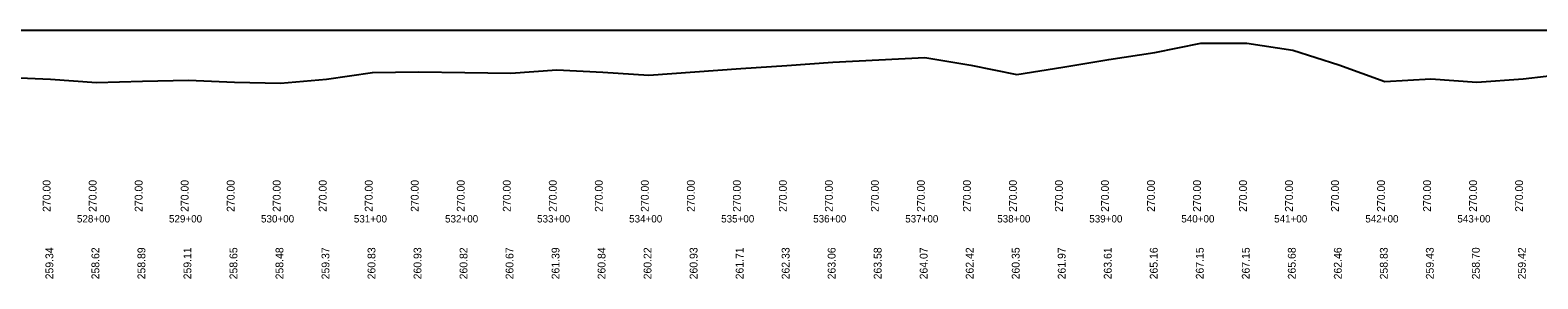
# Model space of a CAD drawing. Extents: x 1354 to 11940, y 17935 to 18885.
# Drawn here: x 6668 to 8306, y 17938 to 18209 of the extents above; entities that cross this region are included whole.
import ezdxf

# ---------------------------------------------------------------- set-up
doc = ezdxf.new("R2010")
doc.units = 0
for name, color, linetype in [('Level 40', 7, 'Continuous'), ('Level 42', 7, 'Continuous'), ('Level 43', 7, 'Continuous'), ('Level 45', 7, 'Continuous')]:
    doc.layers.add(name, color=color, linetype=linetype)

msp = doc.modelspace()

# ---------------------------------------------------------------- linework, layer by layer
at = {"layer": 'Level 40'}
msp.add_lwpolyline([(6639.7, 18157.3), (6689.7, 18155.2), (6739.7, 18151.6), (6789.7, 18153), (6839.7, 18154), (6889.7, 18151.8), (6939.7, 18150.9), (6989.7, 18155.3), (7039.7, 18162.6), (7089.7, 18163.2), (7139.7, 18162.6), (7189.7, 18161.8), (7239.7, 18165.4), (7289.7, 18162.7), (7339.7, 18159.6), (7389.7, 18163.1), (7439.7, 18167), (7489.7, 18170.2), (7539.7, 18173.8), (7589.7, 18176.4), (7639.7, 18178.8), (7689.7, 18170.6), (7739.7, 18160.2), (7789.7, 18168.3), (7839.7, 18176.5), (7889.7, 18184.3), (7939.7, 18194.3), (7989.7, 18194.3), (8039.7, 18186.9), (8089.7, 18170.8), (8139.7, 18152.7), (8189.7, 18155.6), (8239.7, 18152), (8289.7, 18155.6), (8339.7, 18161.4)], dxfattribs=at)
at = {"layer": 'Level 45'}
msp.add_line((4474.7, 18208.5), (8339.7, 18208.5), dxfattribs=at)

# ---------------------------------------------------------------- texts
at = {"layer": 'Level 42'}
for s, p in [('528+00', (6718.4, 17999.5)), ('529+00', (6818.4, 17999.5)), ('530+00', (6918.4, 17999.5)), ('531+00', (7019.3, 17999.5)), ('532+00', (7118.4, 17999.5)), ('533+00', (7218.4, 17999.5)), ('534+00', (7318.4, 17999.5)), ('535+00', (7418.4, 17999.5)), ('536+00', (7518.4, 17999.5)), ('537+00', (7618.4, 17999.5)), ('538+00', (7718.4, 17999.5)), ('539+00', (7818.4, 17999.5)), ('540+00', (7918.4, 17999.5)), ('541+00', (8019.3, 17999.5)), ('542+00', (8118.4, 17999.5)), ('543+00', (8218.4, 17999.5))]:
    msp.add_text(s, height=8, dxfattribs=at).set_placement(p)
at = {"layer": 'Level 43'}
for s, p in [('270.00', (6689.7, 18011)), ('270.00', (6739.7, 18011)), ('270.00', (6789.7, 18011)), ('270.00', (6839.7, 18011)), ('270.00', (6889.7, 18011)), ('270.00', (6939.7, 18011)), ('270.00', (6989.7, 18011)), ('270.00', (7039.7, 18011)), ('270.00', (7089.7, 18011)), ('270.00', (7139.7, 18011)), ('270.00', (7189.7, 18011)), ('270.00', (7239.7, 18011)), ('270.00', (7289.7, 18011)), ('270.00', (7339.7, 18011)), ('270.00', (7389.7, 18011)), ('270.00', (7439.7, 18011)), ('270.00', (7489.7, 18011)), ('270.00', (7539.7, 18011)), ('270.00', (7589.7, 18011)), ('270.00', (7639.7, 18011)), ('270.00', (7689.7, 18011)), ('270.00', (7739.7, 18011)), ('270.00', (7789.7, 18011)), ('270.00', (7839.7, 18011)), ('270.00', (7889.7, 18011)), ('270.00', (7939.7, 18011)), ('270.00', (7989.7, 18011)), ('270.00', (8039.7, 18011)), ('270.00', (8089.7, 18011)), ('270.00', (8139.7, 18011)), ('270.00', (8189.7, 18011)), ('270.00', (8239.7, 18011)), ('270.00', (8289.7, 18011)), ('259.34', (6692.7, 17937.7)), ('260.84', (7292.7, 17937.7)), ('258.62', (6742.7, 17937.7)), ('258.89', (6792.7, 17937.7)), ('259.11', (6842.7, 17937.7)), ('258.65', (6892.7, 17937.7)), ('258.48', (6942.7, 17937.7)), ('259.37', (6992.7, 17937.7)), ('260.83', (7042.7, 17937.7)), ('260.93', (7092.7, 17937.7)), ('260.82', (7142.7, 17937.7)), ('260.67', (7192.7, 17937.7)), ('261.39', (7242.7, 17937.7)), ('260.22', (7342.7, 17937.7)), ('260.93', (7392.7, 17937.7)), ('261.71', (7442.7, 17937.7)), ('262.33', (7492.7, 17937.7)), ('263.06', (7542.7, 17937.7)), ('263.58', (7592.7, 17937.7)), ('264.07', (7642.7, 17937.7)), ('262.42', (7692.7, 17937.7)), ('260.35', (7742.7, 17937.7)), ('261.97', (7792.7, 17937.7)), ('263.61', (7842.7, 17937.7)), ('265.16', (7892.7, 17937.7)), ('267.15', (7942.7, 17937.7)), ('267.15', (7992.7, 17937.7)), ('265.68', (8042.7, 17937.7)), ('262.46', (8092.7, 17937.7)), ('258.83', (8142.7, 17937.7)), ('259.43', (8192.7, 17937.7)), ('258.70', (8242.7, 17937.7)), ('259.42', (8292.7, 17937.7))]:
    msp.add_text(s, height=8.5, rotation=90, dxfattribs=at).set_placement(p)

doc.saveas('drawing.dxf')
